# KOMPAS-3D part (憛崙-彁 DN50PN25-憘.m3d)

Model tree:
1. Объединить компоненты:1  (labels: СЕНС-ПР DN50PN25)
2. Эскиз:1
3. Операция выдавливания:1
     Расстояние 1 = 14
4. Фаска:1
     Угол = 45; Длина 1 = 2; Длина 2 = 2

Referenced files in D:\Савин\!СЕНСОР\3D для заказчика\!Новый перечень\СЕНС-ПР\1. СЕНС-ПР\DN50\: СЕНС-ПР DN50PN25.a3d
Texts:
  СЕНС-ПР DN50PN25-СВ
  СЕНС-ПР DN50PN25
